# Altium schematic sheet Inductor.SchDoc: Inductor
size A; DocumentNumber: 1; SheetNumber: 1; SheetTotal: 1
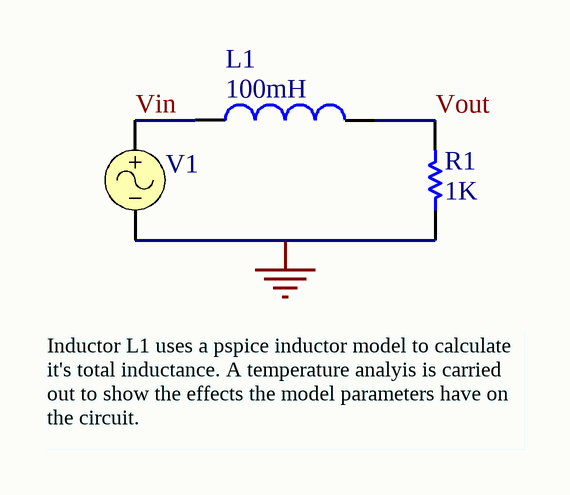
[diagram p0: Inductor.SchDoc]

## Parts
L1  value 100mH  [INDC1005-0402]  (hidden comment: Inductor)
R1  value 1K  [AXIAL-0.3]  (hidden comment: Res1)
V1  VSIN  (value not drawn)

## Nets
GND: R1.1 V1.2
Vin: L1.1 V1.1
Vout: L1.2 R1.2

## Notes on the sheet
- Inductor L1 uses a pspice inductor model to calculate it's total inductance. A temperature analyis is carried out to show the effects the model parameters have on the circuit.

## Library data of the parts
L1 = Inductor: Code_IEC: 1005
R1 = Res1: Resistor
V1 = VSIN: Sinusoidal Voltage Source; Note: PCB Footprint - Not required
